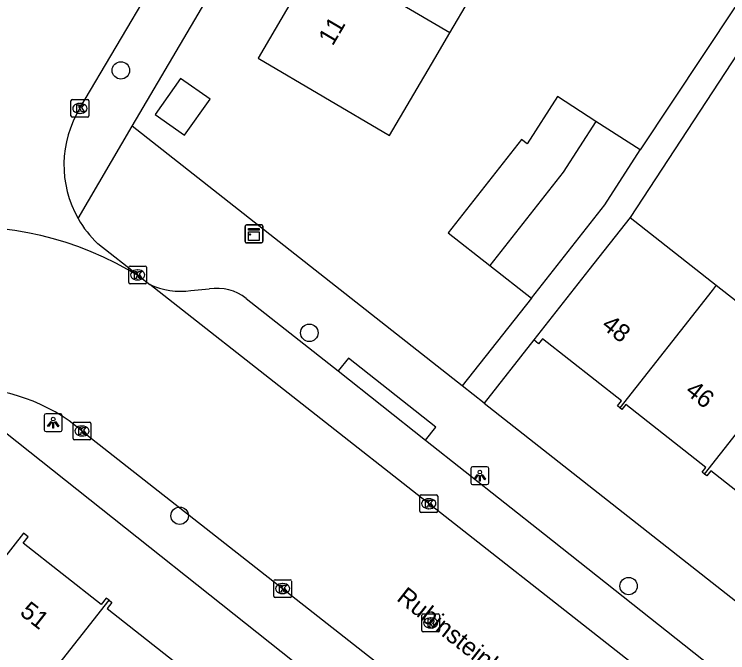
# Model space of a CAD drawing. Extents: x 159222 to 160346, y 381249 to 382166.
# Drawn here: x 160093.85 to 160133.82, y 381952.28 to 381988.06 of the extents above; entities that cross this region are included whole.
import ezdxf

# ---------------------------------------------------------------- set-up
doc = ezdxf.new("R2010")
doc.units = 0
for name, color, linetype in [('IMGEO_Boom', 7, 'Continuous'), ('IMGEO_Kast', 7, 'Continuous'), ('IMGEO_Kolk', 7, 'Continuous'), ('IMGEO_Lichtpunt', 7, 'Continuous'), ('IMGEO_Openbare_ruimte_label', 7, 'Continuous'), ('IMGEO_Pand', 7, 'Continuous'), ('IMGEO_Pand_nummerreeks', 7, 'Continuous'), ('IMGEO_Rijbaan_lokaal_gesloten', 7, 'Continuous'), ('IMGEO_Rijbaan_lokaal_open', 7, 'Continuous'), ('IMGEO_Rioolput', 7, 'Continuous'), ('IMGEO_Voetpad_open', 7, 'Continuous')]:
    doc.layers.add(name, color=color, linetype=linetype)

msp = doc.modelspace()

# ---------------------------------------------------------------- linework, layer by layer
at = {"layer": 'IMGEO_Boom'}
for centre in [(160099.826, 381984.911), (160110.381, 381970.206), (160103.116, 381959.953), (160128.263, 381956.012)]:
    msp.add_circle(centre, 0.489, dxfattribs=at)
at = {"layer": 'IMGEO_Kast'}
for p, q in [((160106.779, 381975.327), (160106.779, 381976.168)), ((160106.779, 381976.168), (160106.779, 381975.327)), ((160106.854, 381976.252), (160107.695, 381976.252)), ((160107.695, 381976.252), (160106.854, 381976.252)), ((160107.779, 381976.177), (160107.779, 381975.336)), ((160107.779, 381975.336), (160107.779, 381976.177)), ((160107.704, 381975.252), (160106.863, 381975.252)), ((160106.863, 381975.252), (160107.704, 381975.252))]:
    msp.add_line(p, q, dxfattribs=at)
for points in [[(160106.974, 381976.042), (160107.574, 381976.042), (160107.574, 381975.957), (160106.974, 381975.957), (160106.974, 381976.042)], [(160106.974, 381975.867), (160107.574, 381975.867), (160107.574, 381975.378), (160106.974, 381975.378), (160106.974, 381975.867)]]:
    msp.add_lwpolyline(points, dxfattribs=at)
msp.add_circle((160107.058, 381975.716), 0.0377, dxfattribs=at)
for centre, start, end in [((160106.857, 381976.174), 92.4484, 184.2845), ((160106.857, 381976.174), 92.4484, 184.2845), ((160107.701, 381976.174), 2.4484, 94.2845), ((160107.701, 381976.174), 2.4484, 94.2845), ((160106.857, 381975.33), 182.4484, 274.2845), ((160106.857, 381975.33), 182.4484, 274.2845), ((160107.701, 381975.33), 272.4484, 4.2845), ((160107.701, 381975.33), 272.4484, 4.2845)]:
    msp.add_arc(centre, 0.0779, start, end, dxfattribs=at)
at = {"layer": 'IMGEO_Kolk'}
for p, q in [((160097.029, 381982.358), (160097.029, 381983.21)), ((160097.104, 381983.284), (160097.956, 381983.284)), ((160098.03, 381983.21), (160098.03, 381982.358)), ((160097.517, 381983.064), (160097.542, 381983.064)), ((160097.54, 381982.504), (160097.515, 381982.504)), ((160097.956, 381982.284), (160097.104, 381982.284)), ((160100.338, 381973.949), (160101.19, 381973.949)), ((160100.263, 381973.023), (160100.263, 381973.875)), ((160100.751, 381973.729), (160100.776, 381973.729)), ((160101.264, 381973.875), (160101.264, 381973.023)), ((160100.774, 381973.169), (160100.749, 381973.169)), ((160101.19, 381972.949), (160100.338, 381972.949)), ((160097.147, 381964.277), (160097.147, 381965.129)), ((160097.222, 381965.203), (160098.074, 381965.203)), ((160098.148, 381965.129), (160098.148, 381964.277)), ((160097.635, 381964.983), (160097.66, 381964.983)), ((160097.658, 381964.423), (160097.633, 381964.423)), ((160098.074, 381964.203), (160097.222, 381964.203)), ((160116.645, 381961.13), (160117.497, 381961.13)), ((160116.57, 381960.204), (160116.57, 381961.056)), ((160117.058, 381960.91), (160117.083, 381960.91)), ((160117.571, 381961.056), (160117.571, 381960.204)), ((160117.081, 381960.35), (160117.056, 381960.35)), ((160117.497, 381960.13), (160116.645, 381960.13)), ((160108.462, 381956.371), (160109.314, 381956.371)), ((160108.387, 381955.445), (160108.387, 381956.297)), ((160108.875, 381956.151), (160108.9, 381956.151)), ((160109.388, 381956.297), (160109.388, 381955.445)), ((160108.898, 381955.591), (160108.873, 381955.591)), ((160109.314, 381955.371), (160108.462, 381955.371))]:
    msp.add_line(p, q, dxfattribs=at)
for points in [[(160097.029, 381982.358), (160097.029, 381983.21)], [(160097.104, 381983.284), (160097.956, 381983.284)], [(160098.03, 381983.21), (160098.03, 381982.358)], [(160097.35, 381982.984), (160097.473, 381982.984), (160097.473, 381982.833), (160097.603, 381982.984), (160097.767, 381982.984), (160097.621, 381982.833), (160097.774, 381982.584), (160097.622, 381982.584), (160097.537, 381982.748), (160097.473, 381982.681), (160097.473, 381982.584), (160097.35, 381982.584), (160097.35, 381982.984)], [(160097.956, 381982.284), (160097.104, 381982.284)], [(160100.338, 381973.949), (160101.19, 381973.949)], [(160100.263, 381973.023), (160100.263, 381973.875)], [(160100.584, 381973.649), (160100.707, 381973.649), (160100.707, 381973.498), (160100.837, 381973.649), (160101.001, 381973.649), (160100.855, 381973.498), (160101.008, 381973.249), (160100.856, 381973.249), (160100.771, 381973.413), (160100.707, 381973.346), (160100.707, 381973.249), (160100.584, 381973.249), (160100.584, 381973.649)], [(160101.264, 381973.875), (160101.264, 381973.023)], [(160101.19, 381972.949), (160100.338, 381972.949)], [(160097.147, 381964.277), (160097.147, 381965.129)], [(160097.222, 381965.203), (160098.074, 381965.203)], [(160098.148, 381965.129), (160098.148, 381964.277)], [(160097.468, 381964.903), (160097.591, 381964.903), (160097.591, 381964.752), (160097.721, 381964.903), (160097.885, 381964.903), (160097.739, 381964.752), (160097.892, 381964.503), (160097.74, 381964.503), (160097.655, 381964.667), (160097.591, 381964.6), (160097.591, 381964.503), (160097.468, 381964.503), (160097.468, 381964.903)], [(160098.074, 381964.203), (160097.222, 381964.203)], [(160116.645, 381961.13), (160117.497, 381961.13)], [(160116.57, 381960.204), (160116.57, 381961.056)], [(160116.891, 381960.83), (160117.014, 381960.83), (160117.014, 381960.679), (160117.144, 381960.83), (160117.308, 381960.83), (160117.162, 381960.679), (160117.315, 381960.43), (160117.163, 381960.43), (160117.078, 381960.594), (160117.014, 381960.527), (160117.014, 381960.43), (160116.891, 381960.43), (160116.891, 381960.83)], [(160117.571, 381961.056), (160117.571, 381960.204)], [(160117.497, 381960.13), (160116.645, 381960.13)], [(160108.462, 381956.371), (160109.314, 381956.371)], [(160108.387, 381955.445), (160108.387, 381956.297)], [(160108.708, 381956.071), (160108.831, 381956.071), (160108.831, 381955.92), (160108.961, 381956.071), (160109.125, 381956.071), (160108.979, 381955.92), (160109.132, 381955.671), (160108.98, 381955.671), (160108.895, 381955.835), (160108.831, 381955.768), (160108.831, 381955.671), (160108.708, 381955.671), (160108.708, 381956.071)], [(160109.388, 381956.297), (160109.388, 381955.445)], [(160109.314, 381955.371), (160108.462, 381955.371)]]:
    msp.add_lwpolyline(points, dxfattribs=at)
for centre, start, end in [((160097.106, 381983.208), 91.552, 178.448), ((160097.106, 381983.208), 91.552, 178.448), ((160097.954, 381983.208), 1.552, 88.448), ((160097.954, 381983.208), 1.552, 88.448), ((160097.106, 381982.36), 181.552, 268.448), ((160097.106, 381982.36), 181.552, 268.448), ((160097.954, 381982.36), 271.552, 358.448), ((160097.954, 381982.36), 271.552, 358.448), ((160100.34, 381973.873), 91.552, 178.448), ((160100.34, 381973.873), 91.552, 178.448), ((160101.188, 381973.873), 1.552, 88.448), ((160101.188, 381973.873), 1.552, 88.448), ((160100.34, 381973.025), 181.552, 268.448), ((160100.34, 381973.025), 181.552, 268.448), ((160101.188, 381973.025), 271.552, 358.448), ((160101.188, 381973.025), 271.552, 358.448), ((160097.224, 381965.127), 91.552, 178.448), ((160097.224, 381965.127), 91.552, 178.448), ((160098.072, 381965.127), 1.552, 88.448), ((160098.072, 381965.127), 1.552, 88.448), ((160097.224, 381964.279), 181.552, 268.448), ((160097.224, 381964.279), 181.552, 268.448), ((160098.072, 381964.279), 271.552, 358.448), ((160098.072, 381964.279), 271.552, 358.448), ((160116.647, 381961.054), 91.552, 178.448), ((160116.647, 381961.054), 91.552, 178.448), ((160117.495, 381961.054), 1.552, 88.448), ((160117.495, 381961.054), 1.552, 88.448), ((160116.647, 381960.206), 181.552, 268.448), ((160116.647, 381960.206), 181.552, 268.448), ((160117.495, 381960.206), 271.552, 358.448), ((160117.495, 381960.206), 271.552, 358.448), ((160108.464, 381956.295), 91.552, 178.448), ((160108.464, 381956.295), 91.552, 178.448), ((160109.312, 381956.295), 1.552, 88.448), ((160109.312, 381956.295), 1.552, 88.448), ((160108.464, 381955.447), 181.552, 268.448), ((160108.464, 381955.447), 181.552, 268.448), ((160109.312, 381955.447), 271.552, 358.448), ((160109.312, 381955.447), 271.552, 358.448)]:
    msp.add_arc(centre, 0.0765, start, end, dxfattribs=at)
for centre, major_axis, ratio, start_param, end_param in [((160097.516, 381982.784), (-0.387, 0.002), 0.722429, 4.712389, 7.853982), ((160097.541, 381982.784), (-0.39, 0.002), 0.717154, 1.570796, 4.712389), ((160100.75, 381973.449), (-0.387, 0.002), 0.722429, 4.712389, 7.853982), ((160100.775, 381973.449), (-0.39, 0.002), 0.717154, 1.570796, 4.712389), ((160097.634, 381964.703), (-0.387, 0.002), 0.722429, 4.712389, 7.853982), ((160097.659, 381964.703), (-0.39, 0.002), 0.717154, 1.570796, 4.712389), ((160117.057, 381960.63), (-0.387, 0.002), 0.722429, 4.712389, 7.853982), ((160117.082, 381960.63), (-0.39, 0.002), 0.717154, 1.570796, 4.712389), ((160108.874, 381955.871), (-0.387, 0.002), 0.722429, 4.712389, 7.853982), ((160108.899, 381955.871), (-0.39, 0.002), 0.717154, 1.570796, 4.712389)]:
    msp.add_ellipse(centre, major_axis=major_axis, ratio=ratio, start_param=start_param, end_param=end_param, dxfattribs=at)
at = {"layer": 'IMGEO_Lichtpunt'}
for p, q in [((160095.538, 381965.572), (160095.538, 381964.765)), ((160095.538, 381965.572), (160095.538, 381964.765)), ((160096.44, 381965.667), (160095.632, 381965.667)), ((160096.44, 381965.667), (160095.632, 381965.667)), ((160096.534, 381964.765), (160096.534, 381965.572)), ((160096.534, 381964.765), (160096.534, 381965.572)), ((160095.632, 381964.671), (160096.44, 381964.671)), ((160095.632, 381964.671), (160096.44, 381964.671)), ((160119.43, 381962.602), (160119.43, 381961.795)), ((160119.43, 381962.602), (160119.43, 381961.795)), ((160120.332, 381962.697), (160119.524, 381962.697)), ((160120.332, 381962.697), (160119.524, 381962.697)), ((160120.426, 381961.795), (160120.426, 381962.602)), ((160120.426, 381961.795), (160120.426, 381962.602)), ((160119.524, 381961.701), (160120.332, 381961.701)), ((160119.524, 381961.701), (160120.332, 381961.701))]:
    msp.add_line(p, q, dxfattribs=at)
for points in [[(160095.912, 381965.236), (160095.951, 381965.208), (160095.763, 381964.946), (160095.725, 381964.973), (160095.912, 381965.236)], [(160096.014, 381965.188), (160096.061, 381965.188), (160096.061, 381964.866), (160096.014, 381964.866), (160096.014, 381965.188)], [(160096.124, 381965.208), (160096.162, 381965.235), (160096.349, 381964.973), (160096.31, 381964.945), (160096.124, 381965.208)], [(160119.804, 381962.266), (160119.843, 381962.238), (160119.655, 381961.976), (160119.617, 381962.003), (160119.804, 381962.266)], [(160119.906, 381962.218), (160119.953, 381962.218), (160119.953, 381961.896), (160119.906, 381961.896), (160119.906, 381962.218)], [(160120.016, 381962.238), (160120.054, 381962.265), (160120.241, 381962.003), (160120.202, 381961.975), (160120.016, 381962.238)]]:
    msp.add_lwpolyline(points, dxfattribs=at)
for centre in [(160096.037, 381965.37), (160119.929, 381962.4)]:
    msp.add_circle(centre, 0.0994, dxfattribs=at)
for centre, start, end in [((160095.632, 381965.572), 90, 180), ((160095.632, 381965.572), 90, 180), ((160096.44, 381965.572), 0, 90), ((160096.44, 381965.572), 0, 90), ((160095.632, 381964.765), 180, 270), ((160095.632, 381964.765), 180, 270), ((160096.44, 381964.765), 270, 0), ((160096.44, 381964.765), 270, 360), ((160119.524, 381962.602), 90, 180), ((160119.524, 381962.602), 90, 180), ((160120.332, 381962.602), 0, 90), ((160120.332, 381962.602), 0, 90), ((160119.524, 381961.795), 180, 270), ((160119.524, 381961.795), 180, 270), ((160120.332, 381961.795), 270, 0), ((160120.332, 381961.795), 270, 360)]:
    msp.add_arc(centre, 0.0946, start, end, dxfattribs=at)
at = {"layer": 'IMGEO_Pand'}
for points in [[(160118.255, 381987.024), (160121.553, 381992.64)], [(160110.881, 381991.35), (160107.512, 381985.605), (160114.88, 381981.268), (160117.408, 381985.582), (160118.255, 381987.024)], [(160118.255, 381987.024), (160110.881, 381991.35)], [(160101.747, 381982.443), (160103.394, 381981.281), (160104.821, 381983.304), (160103.174, 381984.466), (160101.747, 381982.443)], [(160126.436, 381982.056), (160124.283, 381983.444), (160122.583, 381980.796), (160122.273, 381981.04), (160118.16, 381975.813), (160120.49, 381973.98)], [(160126.436, 381982.056), (160124.605, 381979.205), (160120.49, 381973.98)], [(160128.915, 381980.458), (160126.436, 381982.056)], [(160122.82, 381972.146), (160126.933, 381977.373), (160128.915, 381980.458)], [(160128.352, 381976.673), (160126.041, 381973.736), (160122.949, 381969.806)], [(160128.352, 381976.673), (160133.167, 381972.884)], [(160120.49, 381973.98), (160122.82, 381972.146)], [(160133.167, 381972.884), (160132.935, 381972.584), (160127.765, 381966.005)], [(160133.167, 381972.884), (160137.909, 381969.152)], [(160127.765, 381966.005), (160127.639, 381966.104), (160127.86, 381966.385), (160123.434, 381969.867), (160123.219, 381969.593), (160122.949, 381969.806)], [(160132.516, 381962.289), (160137.678, 381968.858), (160137.909, 381969.152)], [(160132.516, 381962.289), (160132.386, 381962.392), (160132.595, 381962.658), (160128.11, 381966.187), (160127.889, 381965.907), (160127.765, 381966.005)], [(160137.235, 381958.572), (160137.099, 381958.679), (160137.326, 381958.967), (160132.872, 381962.473), (160132.647, 381962.186), (160132.516, 381962.289)], [(160099.168, 381955.22), (160099.01, 381955.344), (160098.729, 381954.986), (160094.351, 381958.422), (160094.63, 381958.778), (160094.379, 381958.975), (160089.231, 381952.418), (160087.516, 381950.232), (160092.439, 381946.368), (160092.777, 381946.798), (160094.155, 381948.553)], [(160094.155, 381948.553), (160094.014, 381948.664), (160099.168, 381955.22)], [(160099.168, 381955.22), (160099.323, 381955.098), (160099.05, 381954.749), (160103.465, 381951.284), (160103.738, 381951.631), (160103.903, 381951.502)]]:
    msp.add_lwpolyline(points, dxfattribs=at)
at = {"layer": 'IMGEO_Rijbaan_lokaal_gesloten'}
for points in [[(160100.863, 381973.37), (160101.441, 381972.915)], [(160142.8, 381940.403), (160101.441, 381972.915)], [(160097.652, 381964.702), (160137.256, 381933.585), (160137.357, 381933.503)]]:
    msp.add_lwpolyline(points, dxfattribs=at)
for centre, radius, start, end in [((160091.059, 381957.479), 18.672, 58.3268, 131.1635), ((160091.212, 381957.21), 9.879, 49.318, 92.0711)]:
    msp.add_arc(centre, radius, start, end, dxfattribs=at)
at = {"layer": 'IMGEO_Rijbaan_lokaal_open'}
for points in [[(160097.531, 381982.788), (160107.711, 382000), (160124.728, 382028.051)], [(160100.863, 381973.37), (160098.535, 381975.2)]]:
    msp.add_lwpolyline(points, dxfattribs=at)
for centre, radius, start, end in [((160102.704, 381979.612), 6.07, 148.4481, 209.6799), ((160102.731, 381979.635), 6.105, 209.7433, 226.5855)]:
    msp.add_arc(centre, radius, start, end, dxfattribs=at)
at = {"layer": 'IMGEO_Rioolput'}
for p, q in [((160116.679, 381953.524), (160116.679, 381954.376)), ((160116.754, 381954.45), (160117.606, 381954.45)), ((160117.68, 381954.376), (160117.68, 381953.524)), ((160117.167, 381954.23), (160117.192, 381954.23)), ((160117.19, 381953.67), (160117.165, 381953.67)), ((160117.606, 381953.45), (160116.754, 381953.45))]:
    msp.add_line(p, q, dxfattribs=at)
for points in [[(160116.679, 381953.524), (160116.679, 381954.376)], [(160116.754, 381954.45), (160117.606, 381954.45)], [(160117.68, 381954.376), (160117.68, 381953.524)], [(160117.268, 381954.148), (160117.016, 381954.15), (160117.016, 381953.75)], [(160117.194, 381954.069), (160117.14, 381954.069), (160117.14, 381953.988)], [(160117.14, 381953.988), (160117.192, 381953.988)], [(160117.016, 381953.75), (160117.14, 381953.75), (160117.14, 381953.912), (160117.151, 381953.912)], [(160117.198, 381953.883), (160117.269, 381953.75), (160117.409, 381953.75), (160117.344, 381953.876)], [(160117.606, 381953.45), (160116.754, 381953.45)]]:
    msp.add_lwpolyline(points, dxfattribs=at)
for centre, radius, start, end in [((160116.756, 381954.374), 0.0765, 91.552, 178.448), ((160116.756, 381954.374), 0.0765, 91.552, 178.448), ((160117.604, 381954.374), 0.0765, 1.552, 88.448), ((160117.604, 381954.374), 0.0765, 1.552, 88.448), ((160117.176, 381954.177), 0.19, 274.7715, 282.9687), ((160117.2, 381953.973), 0.0964, 77.0061, 93.1865), ((160117.214, 381954.03), 0.0378, 276.6634, 79.6772), ((160117.267, 381954.038), 0.109, 350.3612, 89.416), ((160117.265, 381954.038), 0.112, 277.5842, 350.9817), ((160117.15, 381953.859), 0.0533, 26.0293, 88.6989), ((160117.249, 381953.823), 0.108, 29.5134, 73.7905), ((160116.756, 381953.526), 0.0765, 181.552, 268.448), ((160116.756, 381953.526), 0.0765, 181.552, 268.448), ((160117.604, 381953.526), 0.0765, 271.552, 358.448), ((160117.604, 381953.526), 0.0765, 271.552, 358.448)]:
    msp.add_arc(centre, radius, start, end, dxfattribs=at)
for centre, major_axis, ratio, start_param, end_param in [((160117.166, 381953.95), (-0.387, 0.002), 0.722429, 4.712389, 7.853982), ((160117.191, 381953.95), (-0.39, 0.002), 0.717154, 1.570796, 4.712389)]:
    msp.add_ellipse(centre, major_axis=major_axis, ratio=ratio, start_param=start_param, end_param=end_param, dxfattribs=at)
at = {"layer": 'IMGEO_Voetpad_open'}
for points in [[(160100.451, 381981.781), (160111.174, 382000), (160126.924, 382026.759)], [(160134.467, 381988.841), (160134.234, 381988.47), (160128.915, 381980.458)], [(160146.891, 381976.411), (160134.736, 381986.411), (160128.352, 381976.673)], [(160097.43, 381976.606), (160100.451, 381981.781)], [(160118.948, 381967.225), (160100.451, 381981.781)], [(160103.752, 381972.57), (160104.78, 381972.662)], [(160106.851, 381972.132), (160111.993, 381968.07)], [(160122.82, 381972.146), (160118.948, 381967.225)], [(160122.949, 381969.806), (160120.164, 381966.268)], [(160116.887, 381964.196), (160117.457, 381964.915), (160112.566, 381968.792), (160111.993, 381968.07)], [(160111.993, 381968.07), (160116.887, 381964.196)], [(160120.164, 381966.268), (160118.948, 381967.225)], [(160120.164, 381966.268), (160212.178, 381893.858), (160212.838, 381893.504)], [(160091.985, 381965.697), (160135.047, 381931.474)], [(160116.887, 381964.196), (160123.544, 381958.928), (160141.712, 381944.521), (160159.725, 381930.297), (160168.874, 381923.038), (160176.929, 381916.708), (160193.834, 381903.352), (160207.982, 381892.133)]]:
    msp.add_lwpolyline(points, dxfattribs=at)
for centre, radius, start, end in [((160103.194, 381976.744), 4.211, 245.4005, 277.618), ((160105.21, 381970.031), 2.666, 52.0122, 99.2783)]:
    msp.add_arc(centre, radius, start, end, dxfattribs=at)

# ---------------------------------------------------------------- texts
at = {"layer": 'IMGEO_Openbare_ruimte_label'}
msp.add_text('Rubinsteinlaan', height=1, rotation=321.8235, dxfattribs=at).set_placement((160115.215, 381955.245))
at = {"layer": 'IMGEO_Pand_nummerreeks'}
for s, rotation, p in [('11', 59.6068, (160111.686, 381986.24)), ('48', 321.8608, (160126.69, 381970.514)), ('46', 321.8608, (160131.381, 381966.83)), ('51', 321.9098, (160094.111, 381954.442))]:
    msp.add_text(s, height=1, rotation=rotation, dxfattribs=at).set_placement(p)

doc.saveas('drawing.dxf')
